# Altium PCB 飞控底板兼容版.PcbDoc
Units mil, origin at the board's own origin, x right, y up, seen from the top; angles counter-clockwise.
Board outline 1946.25 x 1781.68 mil, 4 copper layers (Top Layer, GND, VCC, Bottom Layer), stack 30.634 mil thick; 58 components, 74 nets, 313 pads, 169 vias.
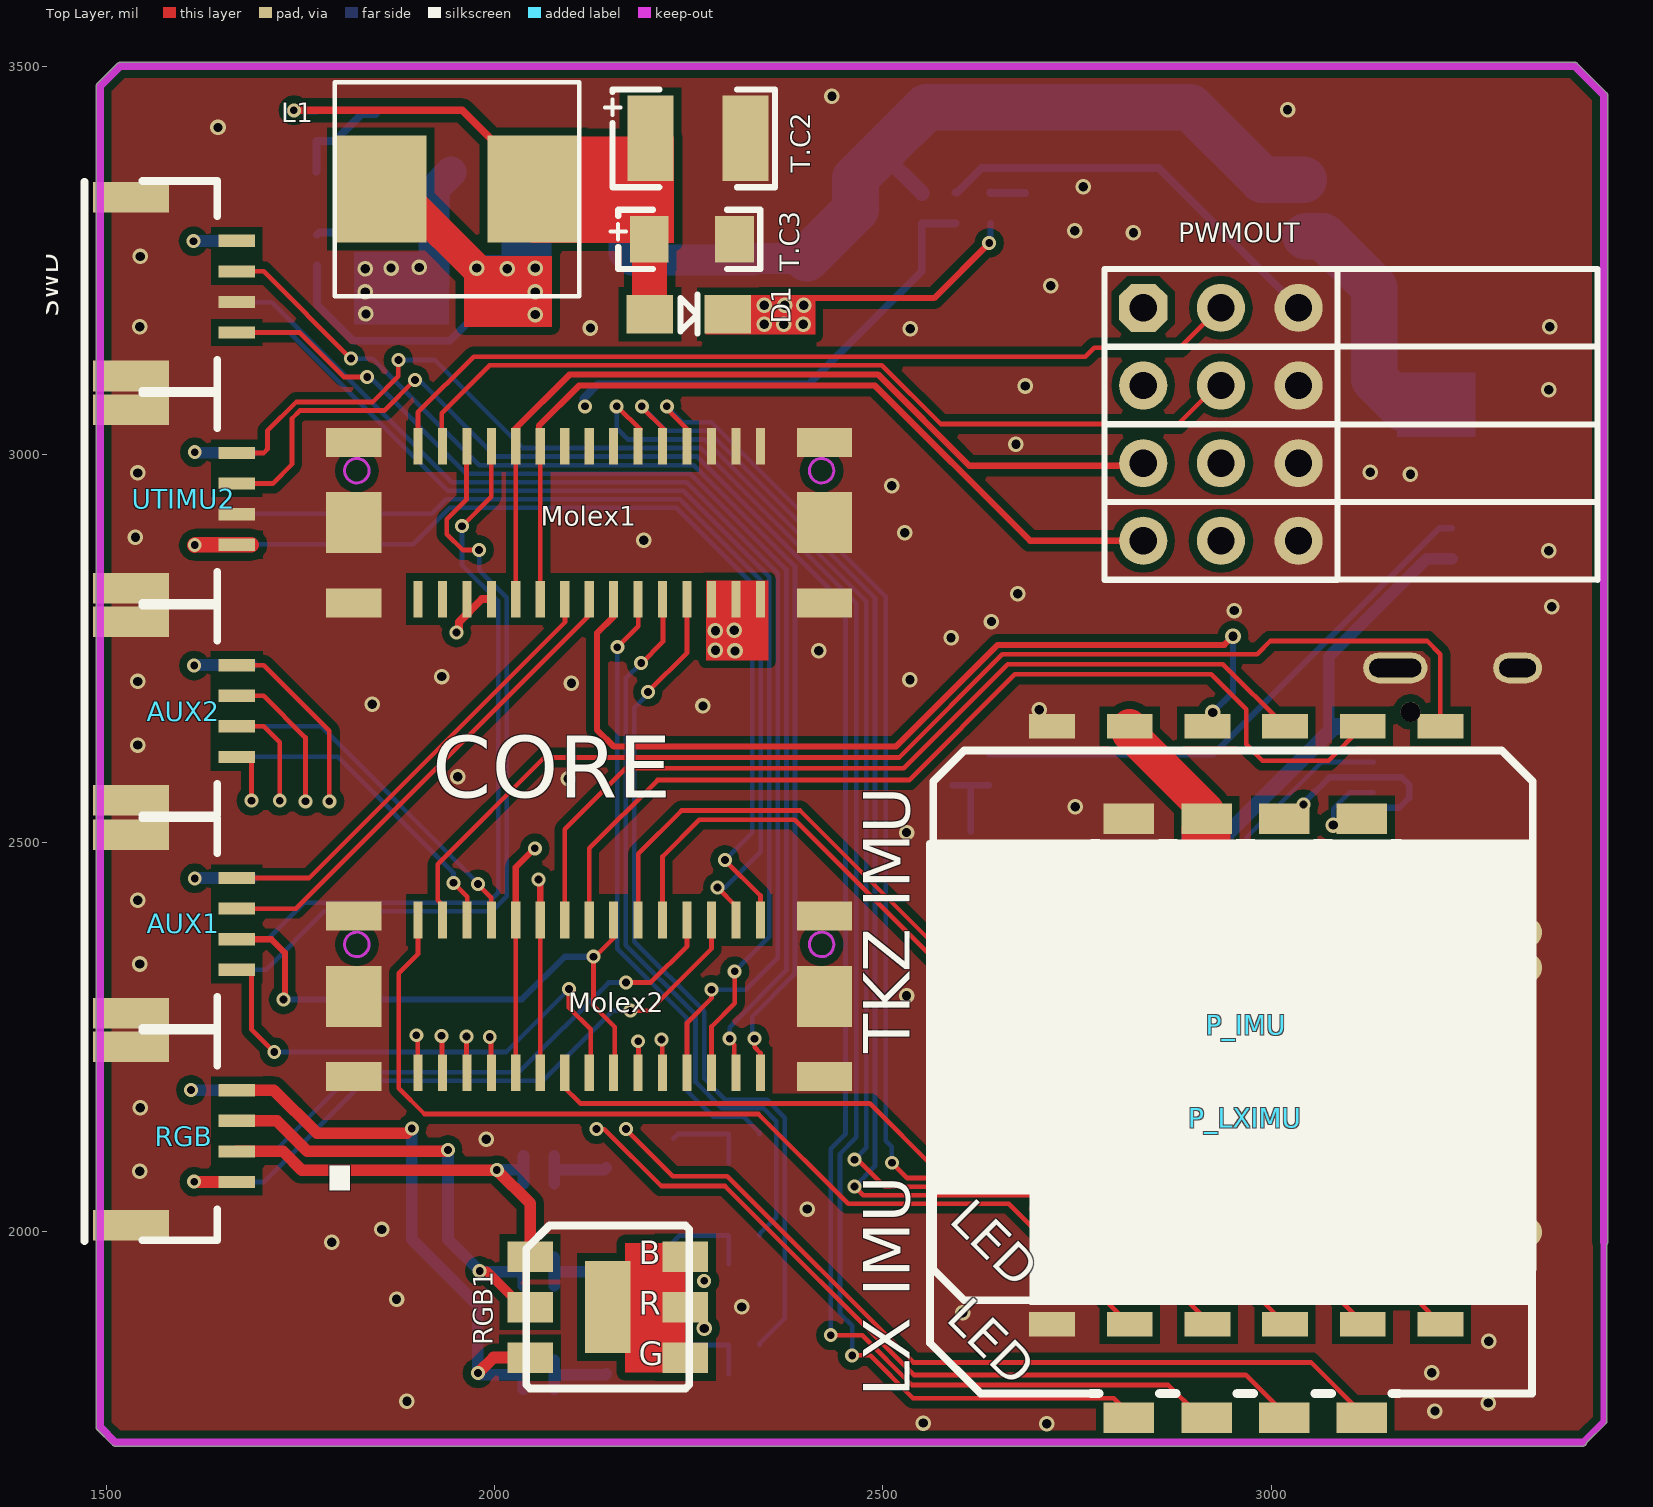
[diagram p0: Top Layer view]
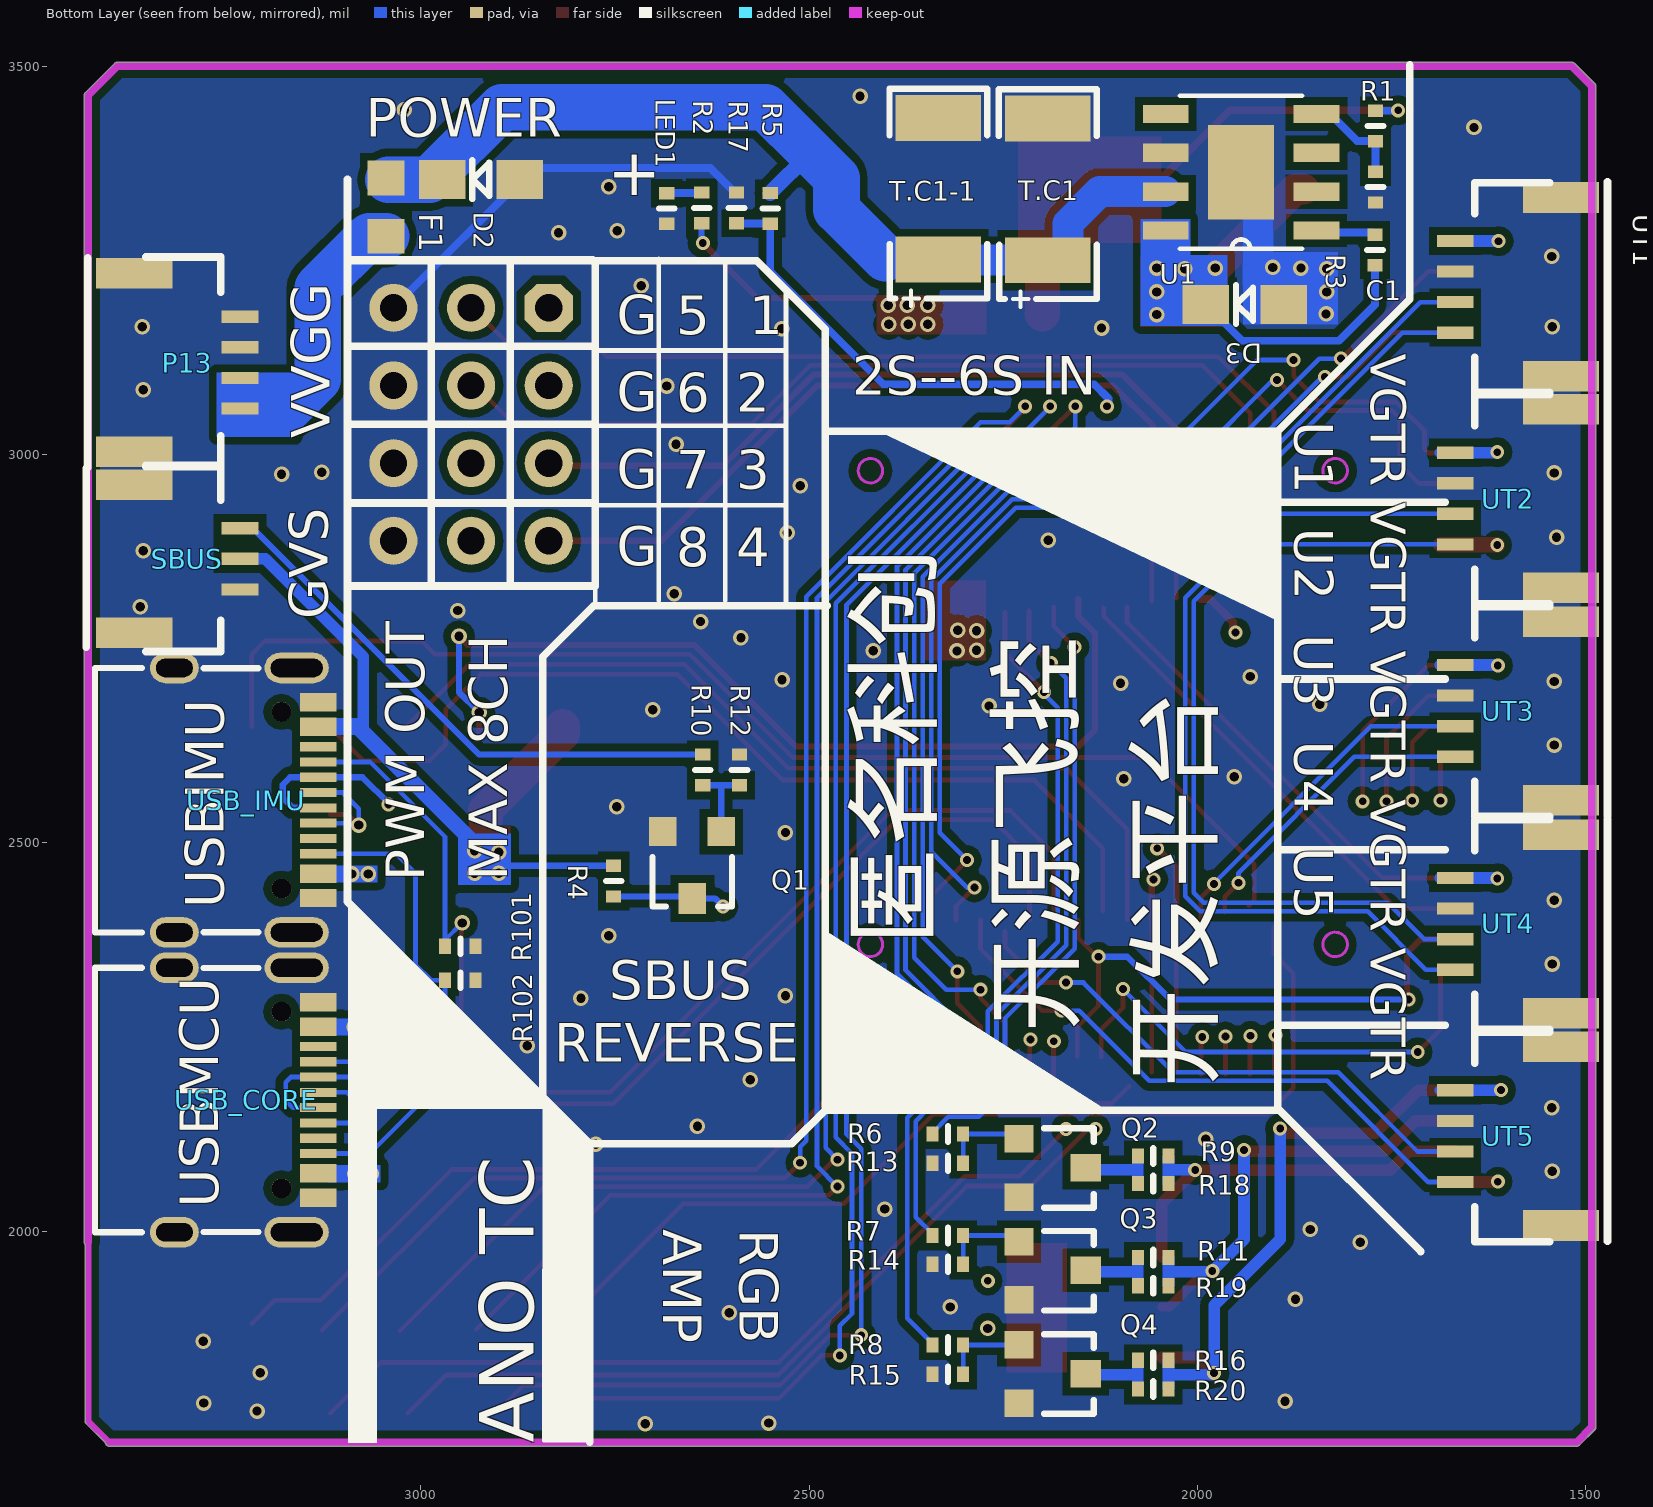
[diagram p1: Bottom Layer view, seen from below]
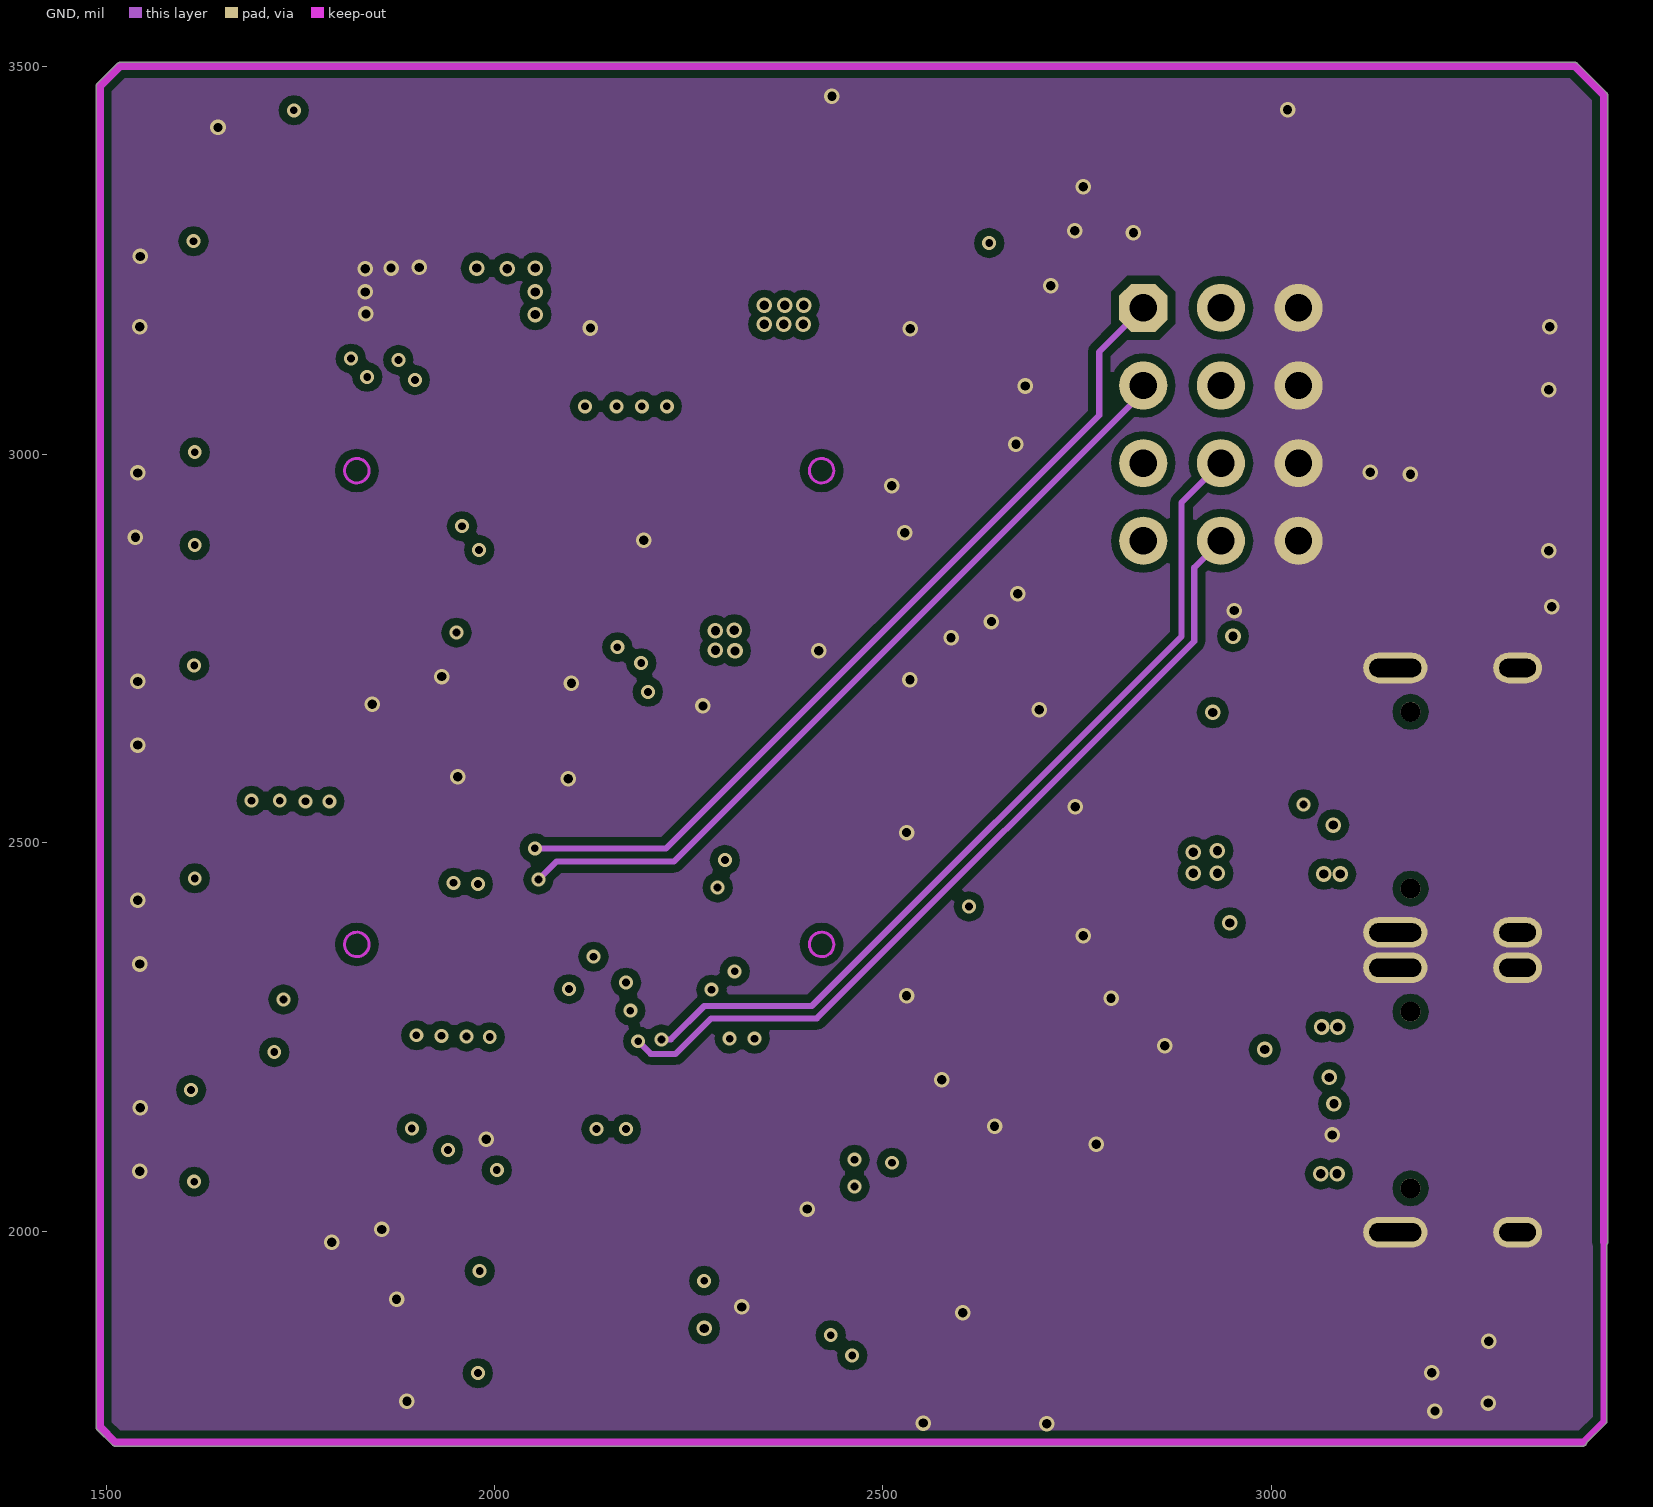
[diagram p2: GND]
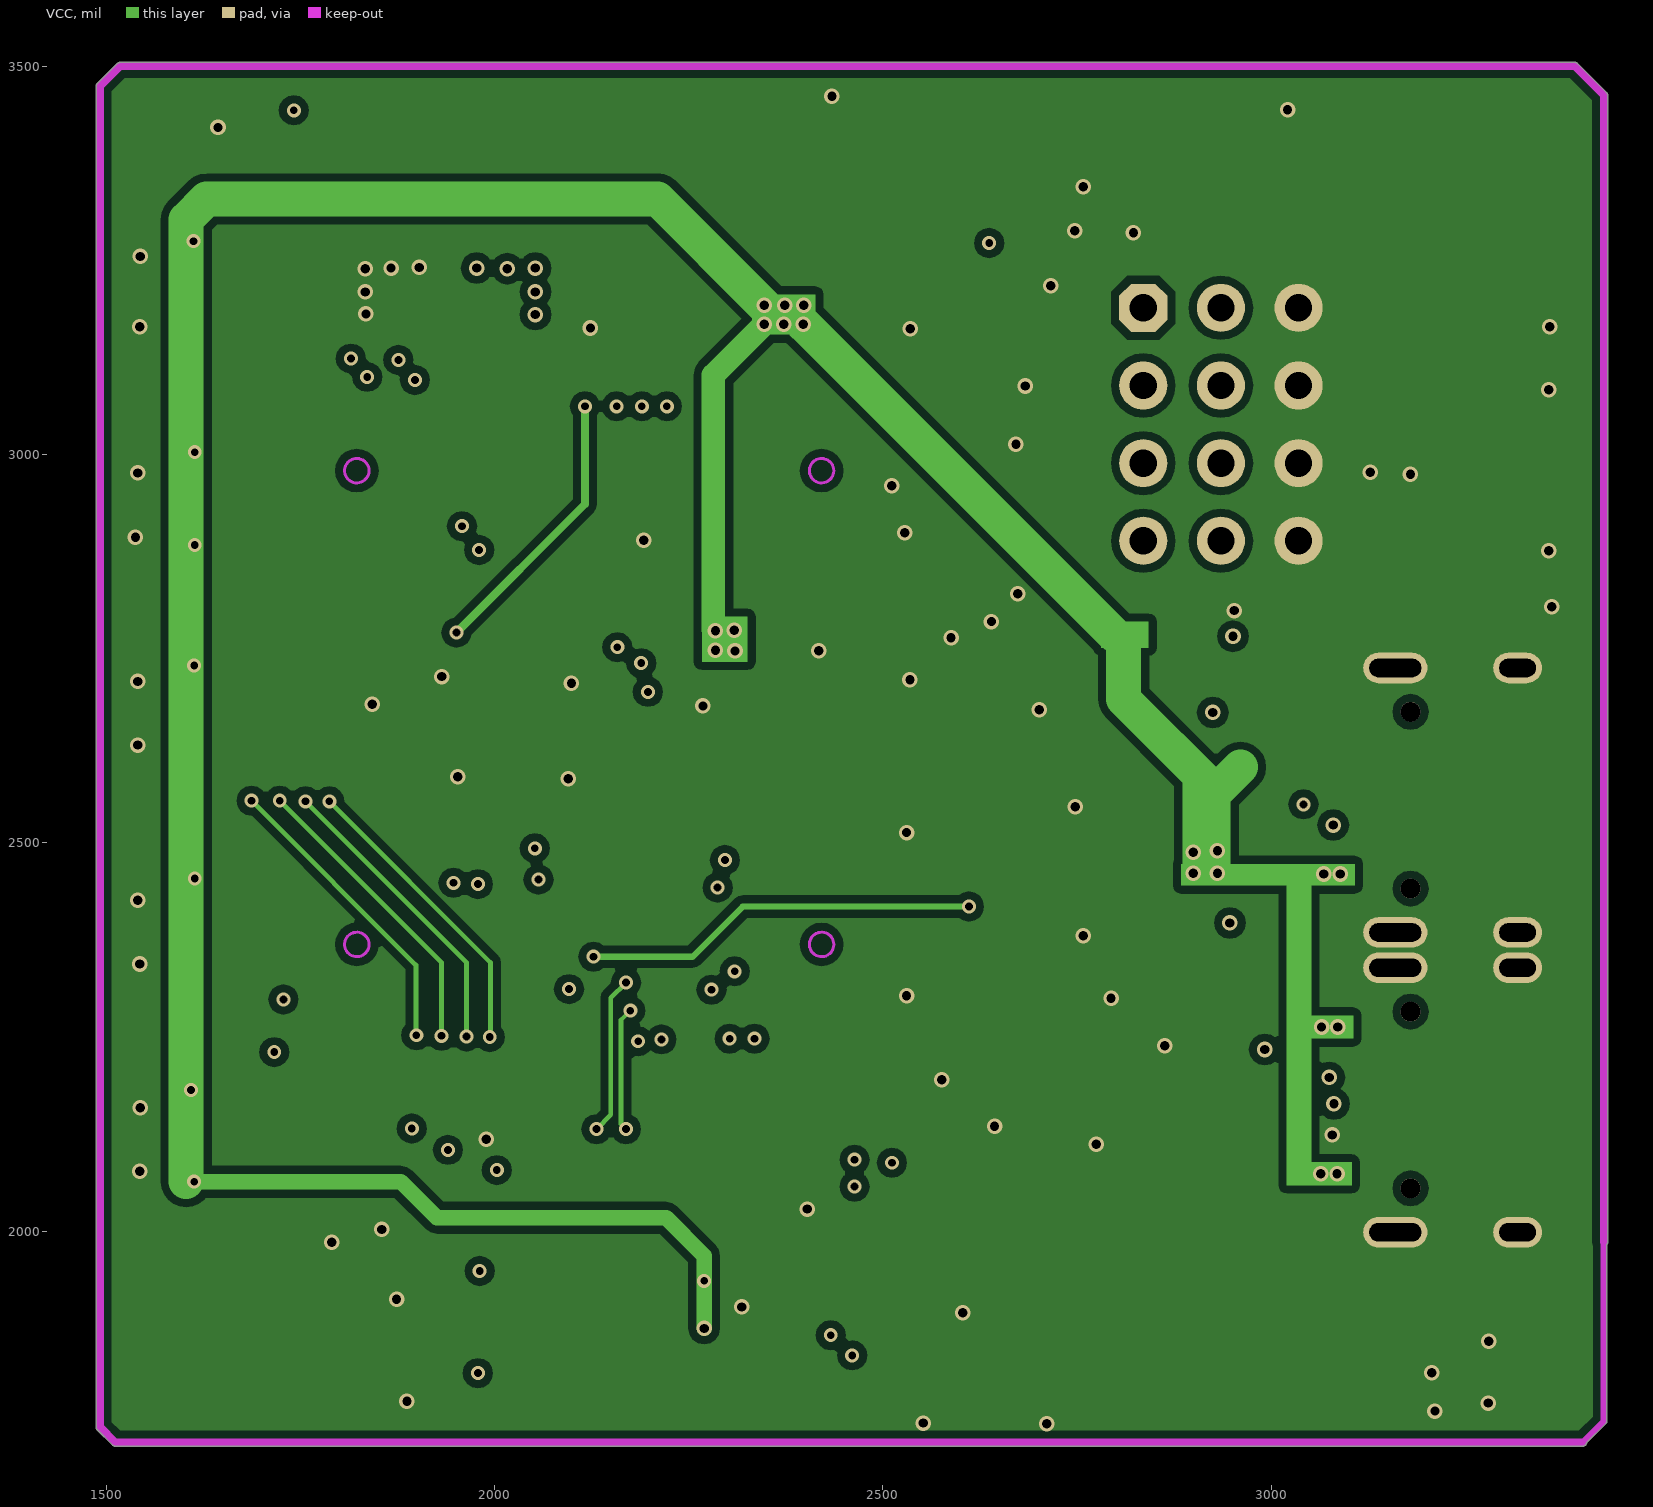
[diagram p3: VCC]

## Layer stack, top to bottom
Top Solder: solder mask 0.4, Solder Resist, Dk 3.5
Top Layer: signal copper 1.4
Dielectric1: core 10, FR-4, Dk 4.2
GND: signal copper 1.417
Dielectric2: prepreg 5, Dk 4.2
VCC: signal copper 1.417
Dielectric3: core 10, Dk 4.2
Bottom Layer: signal copper 1.4
Bottom Solder: solder mask 0.4, Solder Resist, Dk 3.5

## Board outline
1508.11,1724.8 1488.58,1744.33 1488.6,1744.31 cw(c1492.13,1747.87) 1487.11,1747.87 1487.11,3474.13 cw(c1492.13,3474.13) 1488.6,3477.69 1488.58,3477.67 1514.45,3503.55 1514.44,3503.53 cw(c1518,3500) 1518,3505.01 3391,3505.01 cw(c3391,3500) 3394.56,3503.53 3394.55,3503.55 3431.89,3466.2 3431.88,3466.22 cw(c3428.35,3462.65) 3433.36,3462.65 3433.36,1986 cw(c3428.35,1986) 3432.36,1982.99 3432.36,1755.35 cw(c3428.35,1755.35) 3431.17,1752.49 3431.19,1752.51 3406.31,1727.63 cw(c3401.35,1728.35) 3401.35,1723.33 1511.65,1723.33 cw(c1511.65,1728.35)

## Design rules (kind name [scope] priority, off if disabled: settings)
Clearance Clearance_1 [InPolygon] p1: gap=10
Clearance [All] p2: gap=5
ComponentClearance [All] p1: gap=0 collisioncheckmode=3 verticalgap=0 showdistances=FALSE
FabricationTestpoint [(IsPad And (OnTopLayer Or OnBottomLayer))] p1: side=3 testpointundercomponent=TRUE minsize=40 maxsize=100 preferedsize=60 minholesize=0 maxholesize=40 preferedholesize=32 testpointgrid=1 allowsidetop=TRUE allowsidebottom=TRUE usegrid=TRUE gridtolerance=0.01
HoleSize [All] p1: absolutevalues=TRUE maxlimit=196.85 minlimit=1 maxpercent=80.000 minpercent=20.000
HoleToHoleClearance [All] p1: gap=5 allowstackedmicrovias=TRUE
MinimumSolderMaskSliver [All] p1: minsoldermaskwidth=1
PlaneClearance [All] p1: clearance=10
PlaneConnect [All] p1: planeconnectstyle=Direct reliefexpansion=20 reliefentries=4 reliefconductorwidth=10 reliefairgap=10
PolygonConnect [All] p1: connectstyle=Direct reliefconductorwidth=10 reliefentries=4 polygonreliefangle="90 Angle" airgapwidth=10
RoutingVias [All] p1: holewidth=10 width=18 viastyle="Through Hole" minholewidth=10 minwidth=18 maxholewidth=28 maxwidth=50
SilkToSilkClearance [All] p1: silktosilkclearance=0
SilkToSolderMaskClearance [IsPad] p1: minsilkscreentomaskgap=0 clearancetoexposedcopper=TRUE
SolderMaskExpansion [All] p1: expansion=4
Width [All] p1: maxlimit=100 minlimit=4 preferedwidth=5
21 further rules are at their usual default settings.

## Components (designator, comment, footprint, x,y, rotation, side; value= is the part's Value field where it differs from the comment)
AUX1 "AUX_IO" SH_1.0_卧 1540.06,2280.31 r90 top
AUX2 "AUX_IO" SH_1.0_卧 1540.06,2554.32 r90 top
C1 "10nf50v" 0402_small 1771.65,3263.75 r90 bottom
D1 "IN5822" SOD123 2249.61,3181.86 r90 top
D2 "IN5822" SOD123 2922,3353 r270 bottom
D3 "IN5822" SOD123 1938.59,3192.15 r270 bottom
F1 "Comment" 0805_small 3045,3356 r270 bottom
L1 "CD54‐22uH  2A" L-8X7mm-S 1951.97,3341.73 r180 top
LED1 "red" 0402_small 2683.44,3316.54 r270 bottom
Molex1 "MOLEX_30p_母" MOLEX_30p_ĸ 1901.57,3010.79 r0 top
Molex2 "MOLEX_30p_母" MOLEX_30p_ĸ 1901.57,2400.79 r0 top
P13 "power" SH_1.0_卧 3361,3003 r90 bottom
P_IMU "IMU_TKZ" IMU_TKZ_SM2 2603,1911 r0 top
P_LXIMU "IMU_LX" IMU-LX-SM2 2963,2144 r0 top
PWMOUT "HEAD2.54" HEAD1*3*4W 2835.43,3188.98 r270 top
Q1 "si2310" SOT-23 2650.38,2461.42 r0 bottom
Q2 "si2310" SOT-23 2177.17,2081.9 r270 bottom
Q3 "si2310" SOT-23 2177.17,1949.62 r270 bottom
Q4 "si2310" SOT-23 2177.17,1816.55 r270 bottom
R1 "50k" 0402_small 1770.87,3422.86 r270 bottom
R2 "1k" 0402_small 2638.59,3317.35 r270 bottom
R3 "15k" 0402_small 1770.87,3344.12 r270 bottom
R4 "10K" 0402_small 2751.96,2451.17 r90 bottom
R5 "10k 1%" 0402_small 2550.39,3317.31 r90 bottom
R6 "1k" 0402_small 2321.9,2125.2 r0 bottom
R7 "1k" 0402_small 2321.26,1994.48 r180 bottom
R8 "1k" 0402_small 2321.26,1853.54 r180 bottom
R9 "50" 0402_small 2057.47,2096.86 r0 bottom
R10 "1K" 0402_small 2637,2593.71 r270 bottom
R11 "50" 0402_small 2057.47,1966.13 r0 bottom
R12 "10K" 0402_small 2589.75,2593.71 r270 bottom
R13 "10K" 0402_small 2321.26,2087.41 r180 bottom
R14 "10K" 0402_small 2321.26,1957.49 r180 bottom
R15 "10K" 0402_small 2321.26,1815.76 r180 bottom
R16 "50" 0402_small 2057.47,1833.85 r0 bottom
R17 "1k 1%" 0402_small 2593.69,3317.33 r270 bottom
R18 "50" 0402_small 2057.47,2061.41 r0 bottom
R19 "50" 0402_small 2057.47,1929.91 r0 bottom
R20 "50" 0402_small 2057.47,1796.84 r0 bottom
R101 "5.1K" 0402_small 2949,2367 r180 bottom
R102 "5.1K" 0402_small 2949,2323 r180 bottom
RGB "RGB-VBRG" SH_1.0_卧 1540.06,2007.08 r90 top
RGB1 "RGB-LED" zhuixin_5050RGB 2040.93,2002.36 r0 top
SBUS "SBUS" SH_1.0_3P卧 3362,2772 r90 bottom
SWD "swd" SH_1.0_卧 1540.06,3100.78 r90 top
T.C1 "100uf35V" TAN-C(6032-28) 2192.94,3337.79 r180 bottom
T.C1-1 "100uf35V" TAN-C(6032-28) 2333.87,3338.58 r180 bottom
T.C2 "47uf16V" TAN-B(3528-21) 2262.2,3407.11 r270 top
T.C3 "10uf16V" TAN-A(3216-18) 2254.34,3277.14 r180 top
U1 "TPS5430" R-PDSO-G8 1944.06,3268.51 r0 bottom
USB_CORE "Type-C" Type-C 3282,2169 r270 bottom
USB_IMU "Type-C" Type-C 3282,2555 r270 bottom
UT1 "usart1" SH_1.0_卧 1540.06,3331.5 r270 bottom
UT2 "usart2" SH_1.0_卧 1540.06,3058.87 r270 bottom
UT3 "usart3" SH_1.0_卧 1540.06,2785.44 r270 bottom
UT4 "usart4" SH_1.0_卧 1540.06,2511.23 r270 bottom
UT5 "usart5" SH_1.0_卧 1540.06,2237.81 r270 bottom
UTIMU2 "usart_imu" SH_1.0_卧 1540.06,2827.56 r90 top

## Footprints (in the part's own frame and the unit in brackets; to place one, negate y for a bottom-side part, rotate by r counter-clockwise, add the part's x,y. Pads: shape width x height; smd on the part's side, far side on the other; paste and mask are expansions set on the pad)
0402_small [mm]
  rect 0.4x0.5 smd: 1(-0.508,0) 2(0.492,0)
  silkscreen extent -0.01,-0.25 -0.01,0.25, body extent -0.51,-0.25 0.51,0.25, height 0.51
0805_small [mm]
  rect 1.14x1.2 smd: 1(0,0) 2(1.9,0)
HEAD1*3*4W [mil]
  oct 62x62 hole 35: 1(0,0)
  round 62 hole 35: 2(0,100) 3(0,200) 4(100,0) 5(100,100) 6(100,200) 7(200,0) 8(200,100) 9(200,200) 10(300,0) 11(300,100) 12(300,200)
  silkscreen extent -50,-50 350,585, body extent -43,-51 351,249, height 336
IMU-LX-SM2 [mil]
  rect 65x39.37 smd: 1(-146,387) 2(-46,387) 3(54,387) 4(154,387) 5(154,-384) 6(54,-384) 7(-46,-384) 8(-146,-384)
  silkscreen extent -402,-353 373,355
IMU_TKZ_SM2 [mil]
  rect 59.06x31.5 smd: 1(115,739) 2(215,739) 3(315,739) 4(415,739) 5(515,739) 6(615,739) 7(615,-31) 8(515,-31) 9(415,-31) 10(315,-31) 11(215,-31) 12(115,-31)
  silkscreen extent -38,0 734,708
L-8X7mm-S [mm]
  rect 3x3.5 smd: 1(-2.5,0) 2(2.5,0)
  silkscreen extent -4,-3.5 4,3.5, body extent -2.79,-2.67 2.92,2.53, height 4.5
MOLEX_30p_ĸ [mm]
  rect 1.8x0.95 smd: 0(-2.1,-5.125) 0(-2.1,0.125) 0(13.3,-5.125) 0(13.3,0.125)
  rect 1.8x2 smd: 0(-2.1,-2.5) 0(13.3,-2.5)
  rect 0.3x1.2 smd: 1(11.2,0) 2(10.4,0) 3(9.6,0) 4(8.8,0) 5(8,0) 6(7.2,0) 7(6.4,0) 8(5.6,0) 9(4.8,0) 10(4,0) 11(3.2,0) 12(2.4,0) 13(1.6,0) 14(0.8,0) 15(0,0) 16(0,-5) 17(0.8,-5) 18(1.6,-5) 19(2.4,-5) 20(3.2,-5) 21(4,-5) 22(4.8,-5) 23(5.6,-5) 24(6.4,-5) 25(7.2,-5) 26(8,-5) 27(8.8,-5) 28(9.6,-5) 29(10.4,-5) 30(11.2,-5)
  Keep-Out Layer circle w0.1: c-2,-0.8 r0.4
  Keep-Out Layer circle w0.1: c13.2,-0.8 r0.4
R-PDSO-G8 [mil]
  rect 59.06x23.62 smd: 1(-97,-20) 2(-97,-70) 3(-97,-120) 4(-97,-170) 5(97,-170) 6(97,-120) 7(97,-70) 8(97,-20)
  rect 85x122 smd paste-60.5: 9(0,-95)
  silkscreen extent -78,-194 78,4, body extent -122,-194 122,4, height 67
SH_1.0_3P卧 [mm]
  rect 1x2.5 smd: 0(-0.039,0.178) 0(4.803,0.178)
  rect 0.4x1.2 smd: 1(1.381,-3.279) 2(2.381,-3.279) 3(3.381,-3.279)
  silkscreen extent -0.65,-2.64 5.45,1.75
SH_1.0_卧 [mm]
  rect 0.4x1.2 smd: 1(1.432,-3.254) 2(2.432,-3.254) 3(3.432,-3.254) 4(4.432,-3.254)
  rect 1x2.5 smd: 5(0.011,0.203) 5(5.853,0.203)
  silkscreen extent -0.5,-2.62 6.39,1.73, body extent -0.05,-3.43 5.95,1.53, height 3.14
SOD123 [mil]
  rect 50x60 smd: 1(-1.06,49.34) 2(-1.06,-50.66)
  silkscreen extent -26,-12 24,10
SOT-23 [mm]
  rect 0.9x0.95 smd: 1(-0.94,-1.346) 2(0.965,-1.346)
  rect 0.9x1 smd: 3(0,0.838)
  silkscreen extent -1.29,-0.52 1.31,1.1, body extent -1.42,-1.63 1.48,1.17, height 1.3
TAN-A(3216-18) [mil]
  rect 50x60 smd: 1(55,0) 2(-55,0)
  silkscreen extent -88,-38 105,38, body extent -75,-30 75,30, height 39
TAN-B(3528-21) [mm]
  rect 2.8x1.5 smd: 1(0,-1.55) 2(0,1.55)
  silkscreen extent -1.6,-3.05 1.6,2.51
TAN-C(6032-28) [mm]
  rect 2.8x1.5 smd: 1(0,-2.222) 2(0,2.413)
  silkscreen extent -1.6,-3.75 1.6,3.37
Type-C [mm]
  round 0.65 hole 0.65: 0(-2.89,2.6) 0(2.89,2.6)
  oval 1x1.6 hole 0.6 slot 1.2 at 90 deg: 1(4.325,-0.9) 2(-4.325,-0.9)
  oval 1x2.1 hole 0.6 slot 1.7 at 90 deg: 3(-4.325,3.1) 4(4.325,3.1)
  rect 0.3x1.2 smd: A1(-3.35,3.8) A4(-2.55,3.8) A5(-1.25,3.8) A6(-0.25,3.8) A7(0.25,3.8) A8(1.25,3.8) A9(2.55,3.8) A12(3.35,3.8) B1(3.05,3.8) B4(2.25,3.8) B5(1.75,3.8) B6(0.75,3.8) B7(-0.75,3.8) B8(-1.75,3.8) B9(-2.25,3.8) B12(-3.05,3.8)
  silkscreen extent -4.33,-3.5 4.32,1.84, body extent -4.48,-3.5 4.47,4.25, height 3.26
zhuixin_5050RGB [mm]
  rect 1.5x3 smd: 0(2.667,-2.54)
  rect 1.5x1 smd: 1(5.203,-4.191) 2(0.131,-4.191) 3(5.203,-2.54) 4(0.131,-2.54) 5(5.203,-0.889) 6(0.131,-0.889)
  silkscreen extent 0,-5.21 5.33,0.13

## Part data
AUX1 AUX2 P13 RGB SWD UT1 UT2 UT3 UT4 UT5 UTIMU2: library part "Header 4", "Header, 4-Pin"
C1: library part CAP_0402
D1 D2 D3: library part IN5822-SS34, "肖特基二极管"
L1: library part L
LED1: library part D-LED, "LED"
Molex1 Molex2: library part MOLEX_30p_ĸ
PWMOUT: library part HEAD1*3*4
Q1 Q2 Q3 Q4: library part "MOSFET N"
R1 R2 R3 R4 R5 R6 R7 R8 R9 R10 R11 R12 R13 R14 R15 R16 R17 R18 R19 R20: library part Res, "Resistor"
R101 R102: library part R, "贴片电阻"
SBUS: library part HEADER_3P
T.C1 T.C1-1 T.C2 T.C3: library part "Cap TAN", "TAN Capacitor (Radial)"
U1: "9脚与地连接"
USB_CORE USB_IMU: "typeC"

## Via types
v1: diameter 20, hole 12, Top Layer to Bottom Layer, tented both sides, 105 vias
v2: diameter 18, hole 10, Top Layer to Bottom Layer, tented both sides, 64 vias

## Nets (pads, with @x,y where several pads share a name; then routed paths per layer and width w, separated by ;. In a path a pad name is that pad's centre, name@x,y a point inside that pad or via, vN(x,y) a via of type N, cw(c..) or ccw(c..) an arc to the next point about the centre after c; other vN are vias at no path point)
CC1: R101.1 USB_CORE.A5 USB_IMU.A5 | length 703.9
  Top Layer w6: v1(2947,2397) 2948,2396 2948,2278 v1(2992,2234)
  Bottom Layer w6: v1(2947,2397) R101.1@2969,2375 ; R101.1 R101.1@2969,2375 ; v1(2992,2234) 2996,2230 3078,2230 3089.79,2218.21 USB_CORE.A5 ; USB_IMU.A5 3065.21,2604.21 2969,2508 R101.1@2969,2375
CC2: R102.1 USB_CORE.B5 USB_IMU.B5 | length 629.7
  Bottom Layer w6: USB_CORE.B5 3065.9,2100.1 2969,2197 R102.1 2986.99,2322.99 3007,2343 3007,2461.1 3032,2486.1 USB_IMU.B5
DM: Molex2.6 USB_CORE.A7 USB_CORE.B7 | length 1327.5
  Top Layer w6: Molex2.6 2185.04,2485.83 2240.94,2541.73 2393.51,2541.73 2756.24,2179 3056,2179 v1(3075,2198)
  Bottom Layer w6: v1(3075,2198) 3075.53,2198.53 USB_CORE.B7 3167.47,2198.53 3174,2192 3174,2168 3165.16,2159.16 USB_CORE.A7
DP: Molex2.5 USB_CORE.A6 USB_CORE.B6 | length 1243.5
  Top Layer w6: Molex2.5 2216.54,2482.54 2263.92,2529.92 2386.61,2529.92 2704.72,2211.81 2752.54,2164 v1(3081,2164)
  Bottom Layer w6: USB_CORE.B6 3093.53,2139.47 3081,2152 v1(3081,2164) 3095.84,2178.84 USB_CORE.A6
GND: AUX1.5 AUX2.5 D2.1 D3.1 LED1.2 Molex1.0 Molex1.1 Molex1.2 Molex1.3 Molex2.0 P13.3 P13.4 P13.5 P_IMU.1 P_IMU.12 P_LXIMU.1 PWMOUT.3 PWMOUT.6 PWMOUT.9 PWMOUT.12 Q1.2 Q2.2 Q3.2 Q4.2 R3.2 R12.1 R13.1 R14.1 R15.1 R17.1 R101.2 R102.2 RGB.5 SBUS.0 SBUS.1 SWD.2 SWD.5 T.C1-1.2 T.C1.2 T.C2.2 T.C3.2 U1.6 U1.9 USB_CORE.1 USB_CORE.2 USB_CORE.3 USB_CORE.4 USB_CORE.A1 USB_CORE.A12 USB_CORE.B1 USB_CORE.B12 USB_IMU.1 USB_IMU.2 USB_IMU.3 USB_IMU.4 USB_IMU.A1 USB_IMU.A12 USB_IMU.B1 USB_IMU.B12 UT1.2 UT1.5 UT2.2 UT2.5 UT3.2 UT3.5 UT4.2 UT4.5 UT5.2 UT5.5 UTIMU2.2 UTIMU2.5 | length 725.3
  Bottom Layer w10: R17.1 2595.67,3337.33 2627.34,3369 2855.41,3369 PWMOUT.3
  Bottom Layer w40: D3.1 1894.25,3193.22 1922.05,3221.02 1922.05,3341.49 U1.9
  other v1: 2711,1752 2552,1753 3211.02,1768.5 3279.53,1778.74 1887.4,1781.1 3207,1818 3280.32,1858.27 2603,1895 2318.67,1902.57 1874.02,1912.6 1790.55,1985.83 1855.12,2002.36 2402.67,2028.57 1543.31,2077.17 2775,2112 1989.67,2118.57 3079,2124 2644,2135 1544.09,2159.06 2576,2195 2863,2239 2794,2300 2530.71,2303.15 1543.31,2344.09 2758.27,2380.32 1540.94,2425.98 2530.71,2513.39 2748.03,2546.46 2094.97,2582.66 1953,2585 1540.94,2625.98 2701.57,2671.65 2268.5,2676.38 1842.52,2678.74 2099.21,2705.51 1540.94,2707.87 2535,2710 1932.28,2714.17 2417.5,2747.38 2588,2764 2640,2785 2952.76,2799.21 3361.42,2803.94 2674,2821 3357.48,2876.38 2192.13,2889.76 1537.8,2893.7 2528.35,2899.21 2511.81,2959.84 3179.53,2974.8 1540.94,2976.38 3127.56,2977.17 2671.54,3013.32 3357.48,3083.46 2683.54,3088.32 2535.43,3162.2 2123.62,3162.99 1543.31,3164.57 3359.06,3164.57 1834.65,3181.1 1833.86,3209.45 2716.54,3217.32 1833.86,3239.37 1866.93,3240.16 1903.15,3240.94 1544.09,3255.12 2822.83,3285.83 2747.24,3288.19 2758.27,3344.88 1644.09,3421.26 3021.26,3444.09 2434.65,3461.42
GYR_INT: Molex2.22 P_IMU.7 | length 1256.7
  Top Layer w6: Molex2.22@2088,2187 2110.43,2164.57 2483.46,2164.57 2568.55,2079.48 2960.52,2079.48 3129,1911 3188,1911 P_IMU.7@3218,1881
IO_1: AUX1.1 Molex2.23 | length 630.7
  Top Layer w6: AUX1.1@1687.16,2336.7 1687.16,2260.08 v2(1716.54,2230.71) ; v2(2096.06,2311.81) 2096.06,2287.94 2124,2260 Molex2.23@2124,2224
  Bottom Layer w6: v2(1716.54,2230.71) 2014.96,2230.71 v2(2096.06,2311.81)
IO_2: AUX1.2 Molex2.7 Molex2.24 Q1.3 R4.1 | length 1408.9
  Top Layer w6: v2(2127.56,2353.54) v2@2127.56,2351.56 ; Molex2.7 2153.54,2377.54 v2@2127.56,2351.56 ; Molex2.24@2155,2225 2155,2263 2127.56,2290.44 v2@2127.56,2351.56
  Top Layer w8: AUX1.2 1712.91,2376.07 1730.26,2358.72 1730.26,2300.34 v2(1728.35,2298.43)
  VCC w8: v2(2127.56,2353.54) 2255.12,2353.54 2319.68,2418.11 v2(2611.02,2418.11)
  Bottom Layer w8: v2(1728.35,2298.43) 2035.43,2298.43 2090.55,2353.54 v2(2127.56,2353.54) ; v2(2611.02,2418.11) 2621.34,2428.42 Q1.3 2653.12,2431.16 R4.1
IO_3: AUX1.3 Molex1.23 | length 619.8
  Top Layer w6: AUX1.3 1744.44,2415.44 2121,2792 Molex1.23@2121,2803
IO_4: AUX1.4 Molex1.22 | length 578.9
  Top Layer w6: AUX1.4 1761.36,2454.81 2091,2784.45 Molex1.22@2091,2804
IO_5: AUX2.1 Molex2.16 | length 495.2
  Top Layer w6: AUX2.1@1687.16,2610.71 1687.16,2554.57 v2(1687.4,2554.33) ; v2(1899.51,2252.36) 1901.09,2250.79 Molex2.16@1901.09,2201.97
  VCC w6: v2(1687.4,2554.33) 1899,2342.73 v2@1899,2254.33
IO_6: AUX2.2 Molex2.17 | length 576
  Top Layer w6: AUX2.2 1702.91,2650.08 1723.62,2629.37 v2(1723.62,2554.33) ; v2(1931.8,2251.57) 1932.58,2250.79 Molex2.17@1932.58,2201.97
  VCC w6: v2(1723.62,2554.33) 1931.8,2346.16 v2@1931.8,2253.54
IO_7: AUX2.3 Molex2.18 | length 628.4
  Top Layer w6: AUX2.3 1702.91,2689.45 1756.69,2635.67 v2(1756.69,2553.54) ; Molex2.18@1964.08,2201.97 v2(1964.08,2250.79)
  VCC w6: v2(1756.69,2553.54) 1964,2346.24 v2@1964,2252.76
IO_8: AUX2.4 Molex2.19 | length 681.3
  Top Layer w6: AUX2.4 1702.91,2728.82 1787.4,2644.33 v2(1787.4,2553.54) ; v2(1994,2250) 1995.57,2248.43 Molex2.19@1995.57,2201.97
  VCC w6: v2(1787.4,2553.54) 1995,2345.94 v2@1995,2251.97
LED_1: Molex1.27 R8.1 | length 1096.9
  Top Layer w6: v2(2197.64,2694.49) 2248.03,2744.88 Molex1.27@2248.03,2797
  Bottom Layer w6: v2(2197.64,2694.49) 2197.64,2691.39 2180.27,2674.02 2180.27,2372.84 2270,2283.11 2270,2196.69 2297.45,2169.24 2351.04,2169.24 2373.99,2146.29 2373.99,1888.22 2341.15,1855.38 2341.15,1853.53 R8.1
LED_2: Molex1.26 R7.1 | length 946
  Top Layer w6: v2(2188.98,2731.5) 2188.98,2730.98 2217,2759 Molex1.26@2217,2799
  Bottom Layer w6: v2(2188.98,2731.5) 2169.27,2711.79 2169.27,2368.29 2259,2278.56 2259,2192.13 2292.89,2158.24 2346.48,2158.24 2362.99,2141.73 2362.99,2018.17 2341.27,1996.45 R7.1
LED_3: Molex1.25 R6.2 | length 790
  Top Layer w6: v2(2158.27,2751.97) 2159.06,2752.76 2158.66,2753.15 2158.66,2752.66 2185,2779 Molex1.25@2185,2804
  Bottom Layer w6: v2(2158.27,2751.97) 2158.27,2363.73 2248,2274 2248,2181.13 2281.89,2147.24 2321.2,2147.24 2341.27,2127.18 R6.2
NetC1_1: C1.1 D3.2 L1.2 U1.8 | length 611.8
  Top Layer w40: L1.2@1863.78,3341.73 1874.8,3341.73 1996.85,3219.69 2003.15,3213.39 2003.15,3208.66
  Bottom Layer w10: C1.1 1771.64,3192.92 1818.01,3146.56 1942.59,3146.56 D3.2
  Bottom Layer w40: D3.2 1994.25,3193.22 2031.53,3230.5 2031.53,3240.16 U1.8@2031.53,3280.32
  other v1: 2052.76,3180.32 2052.76,3209.45 2016.54,3239.37 1977.17,3240.16 2052.76,3240.16
NetC1_2: C1.2 U1.1 | length 77.7
  Bottom Layer w10: C1.2 1774.34,3285.81 1844.36,3285.81 U1.1
NetD1_1: D1.1 L1.1 R1.1 T.C2.1 T.C3.1 | length 482.6
  Top Layer w10: v2(1741.73,3443.31) 1958.66,3443.31 2050.39,3351.57 L1.1
  Top Layer w45: T.C3.1 2199.8,3276.67 2199.8,3181.26 D1.1
  Bottom Layer w10: v2(1741.73,3443.31) 1742.52,3443.31 1742.96,3442.87 R1.1
NetLED1_1: LED1.1 R2.1 | length 45.2
  Bottom Layer w10: R2.1 2639,3336.95 2683.04,3336.95 LED1.1
NetQ1_1: Q1.1 R10.2 R12.2 | length 107.2
  Bottom Layer w8: R12.2 2613.38,2574.34 ; Q1.1 2613.38,2574.34 ; R10.2 2613.38,2574.34
NetQ2_1: Q2.1 R6.1 R13.2 | length 112.1
  Bottom Layer w6: Q2.1 2236.48,2125.21 R6.1 R13.2
NetQ3_1: Q3.1 R7.2 R14.2 | length 112
  Bottom Layer w6: Q3.1 2238.03,1994.48 R7.2 R14.2
NetQ4_1: Q4.1 R8.2 R15.2 | length 109.5
  Bottom Layer w6: Q4.1 R8.2 R15.2
NetR1_2: R1.2 R3.1 U1.4 | length 130.1
  Bottom Layer w10: R3.1 R1.2 1771.32,3403.94 1794.77,3403.94 1829.35,3438.51 U1.4
OTG_FS_DM: P_LXIMU.3 USB_IMU.A7 USB_IMU.B7 | length 223.9
  Bottom Layer w6: v2@3041.07,2550.27 v2(3041.73,2549.61)
  Bottom Layer w8: v2@3041.07,2550.27 3075.32,2584.53 USB_IMU.B7 3168.47,2584.53 3178,2575 3178,2558 3165.16,2545.16 USB_IMU.A7
OTG_FS_DP: P_LXIMU.4 USB_IMU.A6 USB_IMU.B6 | length 178.1
  Top Layer w6: v1(3080,2523) 3093.61,2536.61 P_LXIMU.4@3116.99,2536.61
  Bottom Layer w6: USB_IMU.B6 3082.47,2525.47 v1(3080,2523) 3080,2544 3100.84,2564.84 USB_IMU.A6
POWER_INPUT: Molex1.18 Molex1.19 R5.1 R17.2 | length 1047.7
  Top Layer w10: v2(1951.18,2770.87) 1954.33,2774.02 1954.33,2784.54 1983.72,2813.94 Molex1.19
  VCC w10: v2(1951.18,2770.87) 2116.54,2936.22 v2(2116.54,3062.2)
  Bottom Layer w10: v2(2116.54,3062.2) 2114.77,3063.97 2114.77,3072.25 2133.07,3090.55 2404.65,3090.55 2550.38,3236.28 R5.1 2550.71,3297.63 2593.37,3297.63 R17.2
PWMOUT_1: Molex2.11 Molex2.20 PWMOUT.1 | length 1417.8
  Top Layer w6: Molex2.20@2027.57,2204.84 Molex2.11@2027.57,2401.69
  Top Layer w8: Molex2.11@2027.57,2401.69 2027.57,2468.57 v2(2052,2493)
  GND w8: v2@2052,2492.91 2220.99,2492.91 2778.74,3050.67 2778.74,3132.28 PWMOUT.1
PWMOUT_2: Molex2.10 Molex2.21 PWMOUT.4 | length 1304
  Top Layer w6: Molex2.21@2059.07,2204.58 Molex2.10@2059.07,2401.43
  Top Layer w8: v2(2056.72,2452.84) 2055.9,2452.84 2059.07,2456.01 Molex2.10@2059.07,2401.43
  GND w8: v2(2056.72,2452.84) 2079.88,2476 2231,2476 2835.43,3080.43 PWMOUT.4
PWMOUT_3: Molex1.11 Molex1.20 PWMOUT.7 | length 1086.2
  Top Layer w6: Molex1.20@2027.57,2814.94 Molex1.11@2027.57,3011.79
  Top Layer w8: Molex1.11@2025.74,3031.74 2097.15,3103.15 2493.98,3103.15 2611.55,2985.57 2832.03,2985.57 PWMOUT.7
PWMOUT_4: Molex1.10 Molex1.21 PWMOUT.10 | length 1087.9
  Top Layer w6: Molex1.21@2059.07,2810.94 Molex1.10@2059.07,3007.79
  Top Layer w8: Molex1.10@2057.54,3028.54 2057.54,3037.54 2108.98,3088.98 2489.76,3088.98 2689.76,2888.98 PWMOUT.10
PWMOUT_5: Molex1.15 PWMOUT.2 | length 1125.1
  Top Layer w6: Molex1.15@1901.57,3019 1901.57,3054.49 1973.24,3126.15 2760.8,3126.15 2772.44,3137.8 2882.68,3137.8 2933.86,3188.98 PWMOUT.2
PWMOUT_6: Molex1.14 PWMOUT.5 | length 1109.4
  Top Layer w6: Molex1.14@1932,3025 1932,3053.42 1993.73,3115.15 2498.95,3115.15 2574.73,3039.37 2880.32,3039.37 2929.92,3088.98 PWMOUT.5
PWMOUT_7: Molex2.26 PWMOUT.8 | length 1173.9
  Top Layer w6: Molex2.26@2215,2202.91 2216.18,2204.09 2216.18,2245.82 v2(2215,2247)
  GND w8: v2(2215,2247) 2227,2247 2270,2290 2408.9,2290 2884.65,2765.75 2884.65,2938.19 PWMOUT.8
PWMOUT_8: Molex2.25 PWMOUT.11 | length 1133.2
  Top Layer w6: v2(2185.08,2244.64) 2188.23,2241.49 2187.87,2241.49 2185.47,2239.09 2185.47,2200.94 Molex2.25@2185.87,2200.54
  GND w8: v2(2185.08,2244.64) 2201.37,2228.35 2233.35,2228.35 2279,2274 2415.2,2274 2901,2759.8 2901,2854.54 PWMOUT.11
R1: Q2.3 R9.2 R18.2 | length 103.9
  Bottom Layer w15: R18.2 2076.83,2079.14 ; R9.2 2076.83,2079.14 ; Q2.3 2141.41,2079.14 2076.83,2079.14
R2: Q3.3 R11.2 R19.2 | length 104.2
  Bottom Layer w15: R19.2 2076.83,1948.03 ; R11.2 2076.83,1948.03 ; Q3.3 2142.58,1948.03 2076.83,1948.03
R3: Q4.3 R16.2 R20.2 | length 104.8
  Bottom Layer w15: R20.2 2076.83,1815.35 ; R16.2 2076.83,1815.35 ; Q4.3 2142.98,1815.35 2076.83,1815.35
R4: R9.1 R18.1 RGB1.6 RGB.2 | length 544.1
  Top Layer w15: RGB.2 1727.87,2102.84 1751.97,2078.74 v2(2003.15,2078.74) 2046.09,2035.8 RGB1.6
  Bottom Layer w15: v2(2003.15,2078.74) 2003.55,2079.14 2037.46,2079.14 ; R18.1 2037.46,2079.14 ; R9.1 2037.46,2079.14
R5: R11.1 R19.1 RGB1.4 RGB.3 | length 638.8
  Top Layer w12: v2(1981.1,1948.82) 1989.78,1948.82 2036.24,1902.36 RGB1.4
  Top Layer w15: RGB.3 1720,2142.21 1758.98,2103.22 1938.66,2103.22 v2(1940.16,2104.72)
  Bottom Layer w15: v2(1940.16,2104.72) 1940.16,1989.76 v2(1981.1,1948.82) 1981.89,1948.03 2037.46,1948.03 ; R19.1 2037.46,1948.03 ; R11.1 2037.46,1948.03
R6: R16.1 R20.1 RGB1.2 RGB.4 | length 773.6
  Top Layer w15: RGB.4 1716.06,2181.58 1771.65,2125.98 1887.4,2125.98 v2(1893.7,2132.28) ; v2(1978.74,1817.32) 1998.77,1837.36 RGB1.2
  Bottom Layer w15: v2(1893.7,2132.28) 1893.7,1989.76 1978.74,1904.72 v2(1978.74,1817.32) 1980.71,1815.35 2037.46,1815.35 ; R20.1 2037.46,1815.35 ; R16.1 2037.46,1815.35
SBUS_IN: R10.1 SBUS.3 | length 716.6
  Bottom Layer w8: R10.1 2925.02,2613.71 3216.44,2905.13 SBUS.3
SPI2_CS1: Molex1.4 P_IMU.8 | length 1867.6
  Top Layer w6: v2@2222.05,3068.2 v2(2222.05,3062.2) 2222.05,3058.95 Molex1.4@2249,3032 ; v2(2511.81,2088.19) 2531.52,2068.48 2931.52,2068.48 P_IMU.8@3127.5,1872.5
  Bottom Layer w6: v2@2222.05,3061.42 2241.97,3041.5 2279.49,3041.5 2504,2816.99 2504,2116.47 2511.81,2108.66 v2(2511.81,2088.19)
SPI2_CS2: Molex1.6 P_IMU.9 | length 1865.7
  Top Layer w6: v2@2157.48,3061.42 2159.06,3059.84 2159.06,3061.13 Molex1.6@2188.19,3032 ; v2(2463.78,2092.13) 2467.72,2092.13 2502.36,2057.48 2841.52,2057.48 P_IMU.9@3027,1872
  Bottom Layer w6: v2@2157.48,3061.42 2157.48,3033.67 2171.65,3019.5 2270.38,3019.5 2479,2810.88 2479,2107.35 v2(2463.78,2092.13)
  other v2: 2157.48,3062.2
SPI2_CS3: Molex1.5 P_IMU.10 | length 1753.7
  Top Layer w6: v2@2189.76,3061.42 2190.55,3060.63 2190.55,3060.45 Molex1.5@2219,3032 ; v2(2463.78,2057.48) 2474.78,2046.48 2756.52,2046.48 P_IMU.10@2929,1874
  Bottom Layer w6: v2@2189.76,3061.42 2220.68,3030.5 2274.94,3030.5 2490,2815.43 2490,2083.7 v2(2463.78,2057.48)
  other v2: 2189.76,3062.2
SPI2_MISO: Molex2.8 P_IMU.5 | length 1260.3
  Top Layer w6: Molex2.8@2122,2412 2122,2492.87 2210.07,2580.93 2533.93,2580.93 2670,2717 2923,2717 2968,2672 2968,2627 2989,2606 3074,2606 P_IMU.5
SPI2_MOSI: Molex2.9 P_IMU.4 | length 1165.3
  Top Layer w6: Molex2.9 2090.55,2517.55 2169,2596 2527,2596 2661,2730 2938,2730 P_IMU.4
SPI2_NSS: Molex2.15 P_IMU.11 | length 1297.1
  Top Layer w6: Molex2.15@1901.57,2392 1901.57,2356.69 1877,2332.12 1877,2184 1910,2151 2340,2151 2455.52,2035.48 2662.52,2035.48 P_IMU.11@2826.5,1871.5
SPI2_SCK: Molex2.14 P_IMU.6 | length 1566.7
  Top Layer w6: Molex2.14@1934,2419 1927,2426 1927,2472.76 2064.24,2610 2521,2610 2654,2743 2982,2743 2999,2760 3201,2760 3218,2743 P_IMU.6
SWCLK_I: Molex2.30 SWD.3 | length 1542.2
  Top Layer w6: SWD.3 1702.91,3235.9 v2(1815.19,3123.62) ; v2(2335,2248) 2335,2237 2342.52,2229.48 Molex2.30@2342.52,2219
  Bottom Layer w6: v2(1815.19,3123.62) 1843.31,3123.62 1980.43,2986.5 2256.71,2986.5 2387,2856.21 2387,2331.29 2332,2276.29 2332,2248 v2(2335,2248)
SWDIO_I: Molex2.29 SWD.1 | length 1517.7
  Top Layer w6: SWD.1 1749.13,3157.16 1806.3,3100 v2(1836.22,3100) ; v2(2303,2248) 2301,2248 2309,2240 Molex2.29@2309,2203.94
  Bottom Layer w6: v2(1836.22,3100) 1839.37,3100 1963.87,2975.5 2252.15,2975.5 2376,2851.65 2376,2335.84 2303,2262.84 v2(2303,2248)
TIM10_CH1: Molex1.24 P_IMU.3 | length 1200.6
  Top Layer w8: Molex1.24 2153.54,2791.54 2132,2770 2132,2646 2154,2624 2517,2624 2648,2755 2940,2755 v1(2951,2766) ; P_IMU.3@2925,2640 v1(2925,2668)
  Bottom Layer w8: v1(2925,2668) 2951,2694 v1(2951,2766)
USART1_RX_I: Molex2.28 UT1.4 | length 1485.5
  Top Layer w6: Molex2.28 2279.53,2263.53 2309.45,2293.45 v2(2309.45,2334.65)
  Bottom Layer w6: UT1.4 1736.7,3157.01 1940.2,2953.5 2243.04,2953.5 2354,2842.54 2354,2379.2 v2(2309.45,2334.65)
USART1_TX_I: Molex2.27 UT1.3 | length 1559
  Top Layer w6: Molex2.27 2248.03,2268.5 2279.53,2300 v2(2279.53,2311.02)
  Bottom Layer w6: UT1.3 1713.07,3196.38 1944.95,2964.5 2247.6,2964.5 2365,2847.09 2365,2352.4 2323.62,2311.02 v2(2279.53,2311.02)
USART2_RX_I: Molex2.1 UT2.4 | length 1175.9
  Top Layer w6: v2(2296.85,2477.95) 2342.52,2432.28 Molex2.1@2342.52,2415
  Bottom Layer w6: UT2.4 1895.39,2884.37 1942.52,2931.5 2233.93,2931.5 2332,2833.43 2332,2513.1 v2(2296.85,2477.95)
USART2_TX_I: Molex2.2 UT2.3 | length 1212.6
  Top Layer w6: v2(2287.4,2442.52) 2285.04,2440.16 2285.04,2444.75 2287.33,2442.45 2311.02,2418.76 Molex2.2
  Bottom Layer w6: UT2.3 1919.21,2923.74 1937.96,2942.5 2238.49,2942.5 2343,2837.98 2343,2488.67 2296.85,2442.52 v2(2287.4,2442.52)
USART3_RX_I: Molex2.13 UT3.4 | length 399
  Top Layer w6: v2(1947.24,2448.57) 1965,2430.82 Molex2.13@1965,2411
  Bottom Layer w6: UT3.4 1798.06,2610.94 1947.24,2461.76 v2(1947.24,2448.57)
USART3_TX_I: Molex2.12 UT3.3 | length 448.6
  Top Layer w6: v2(1978.74,2447) 1996.06,2429.68 Molex2.12
  Bottom Layer w6: UT3.3 1776.87,2650.31 v2@1979.46,2447.72
USART4_RX_I: Molex1.13 UT4.4 | length 1008.7
  Top Layer w6: Molex1.13@1964,2998 1964,2942 1938.58,2916.58 1938.58,2897.64 1959.06,2877.17 v2(1980.32,2877.17)
  Bottom Layer w6: UT4.4 1706.02,2336.73 1781.13,2411.83 1996.39,2411.83 2016,2431.44 2016,2815.5 1980.32,2851.18 v2(1980.32,2877.17)
USART4_TX_I: Molex1.12 UT4.3 | length 957.6
  Top Layer w6: v2(1958.27,2907.87) 1996,2945.61 Molex1.12@1996,2997
  Bottom Layer w6: UT4.3 1708.39,2376.1 1755.12,2422.83 1991.83,2422.83 2005,2436 2005,2810.94 1958.27,2857.67 v2(1958.27,2907.87)
USART5_RX_I: Molex2.3 P_LXIMU.5 UT5.4 | length 2032.2
  Top Layer w6: v2(2169.29,2131.5) 2229.79,2071 2299.67,2071 2539.67,1831 3051.6,1831 P_LXIMU.5@3116.99,1765.61 ; v2(2175,2284) 2200.25,2284 ; 2200.25,2284.25 2279.53,2363.53 Molex2.3
  VCC w6: v2(2169.29,2131.5) 2163,2137.79 2163,2272 v2(2175,2284)
  Bottom Layer w6: UT5.4 1702.91,2063.31 1833.33,2193.72 2062.23,2193.72 2152.5,2284 v2(2175,2284)
USART5_TX_I: Molex2.4 P_LXIMU.6 UT5.3 | length 1949.7
  Top Layer w6: v2(2131.5,2131.5) 2141.5,2131.5 2214.73,2058.27 2296.84,2058.27 2540.11,1815 2967.6,1815 P_LXIMU.6@3016.99,1765.61 ; v2(2169.49,2320.22) 2201.47,2320.22 ; 2201.47,2320.47 2248.03,2367.03 Molex2.4@2248.03,2386
  VCC w6: v2(2131.5,2131.5) 2150,2150 2150,2300.73 v2(2169.49,2320.22)
  Bottom Layer w6: UT5.3 1716.85,2102.68 1818.9,2204.72 2031.5,2204.72 2146.99,2320.22 v2(2169.49,2320.22)
USART_IMU_RX: P_LXIMU.8 UTIMU2.4 | length 2374
  Top Layer w6: UTIMU2.4 1702.91,3002.05 1707.78,3006.93 1707.78,3030.43 1745.05,3067.69 1843.28,3067.69 1876.38,3100.79 v2(1876.38,3121.84) ; v2(2460.63,1840.16) 2483.84,1840.16 2539,1785 2797.6,1785 P_LXIMU.8@2816.99,1765.61
  Bottom Layer w6: v2(1876.38,3121.84) 1923.04,3121.84 2036.39,3008.5 2265.82,3008.5 2466,2808.32 2466,2121 2445,2100 2445,1893.77 2460.63,1878.14 v2(2460.63,1840.16)
USART_IMU_TX: P_LXIMU.7 UTIMU2.3 | length 2467.5
  Top Layer w6: UTIMU2.3 1714.65,2962.68 1739.37,2987.4 1739.37,3046.46 1749.61,3056.69 1858.27,3056.69 v2(1897.64,3096.06) ; v2(2433.07,1866.14) 2473.41,1866.14 2537.56,1802 2867.78,1802 2904.18,1765.61 P_LXIMU.7@2916.99,1765.61
  Bottom Layer w6: v2(1897.64,3096.06) 1903.15,3096.06 2001.72,2997.5 2261.27,2997.5 2452,2806.76 2452,2125 2433.07,2106.07 v2(2433.07,1866.14)
VCC_3.3V: SWD.4
VCC_5.0V: D1.2 Molex1.28 Molex1.29 Molex1.30 P_IMU.2 P_LXIMU.2 R2.2 R4.2 RGB1.0 RGB1.1 RGB1.3 RGB1.5 RGB.1 SBUS.2 USB_CORE.A4 USB_CORE.A9 USB_CORE.B4 USB_CORE.B9 USB_IMU.A4 USB_IMU.A9 USB_IMU.B4 USB_IMU.B9 UT1.1 UT2.1 UT3.1 UT4.1 UT5.1 UTIMU2.1 | length 5724.5
  Top Layer w8: v1(2398.43,3192.13) 2407.81,3201.51 2566.08,3201.51 v2(2637.01,3272.44)
  Top Layer w15: v2(1613.39,2063.78) 1613.7,2063.47 RGB.1
  Top Layer w20: v2(1614.17,2883.46) 1614.65,2883.95 UTIMU2.1 UTIMU2.1@1687.16,2883.95
  Top Layer w45: P_IMU.2 2818,2641 2917,2542 P_LXIMU.2
  VCC w20: 1603.15,2063.78 v2(1613.39,2063.78) 1879.53,2063.78 1925.98,2017.32 2221.26,2017.32 2270.08,1968.5 v2(2270.08,1936.22) v1(2270.08,1874.8)
  VCC w30: v1@2281.89,2774.8 2281.89,3102.36 v1(2347.24,3167.72)
  VCC w45: 1603.15,2063.78 1603.15,2454.33 1603.15,2883.46 1603.15,3274.8 1603.15,3302.77 1629.51,3329.13 2210.24,3329.13 v1(2347.24,3192.13) ; v1(2397.64,3167.72) 2398.43,3167.72 2797.64,2768.5 ; 2810.24,2762.54 2810.24,2685.04 2929.13,2566.14 2960.63,2597.64
  Bottom Layer w8: v2(2637.01,3272.44) 2637.01,3274.8 2638.59,3276.39 R2.2 ; R4.2 2890.47,2470.53
  Bottom Layer w15: v2(1609.45,2181.89) 1609.92,2181.42 UT5.1 UT5.1@1687.16,2181.42 ; v2(1612.6,3274.8) 1612.91,3275.12 UT1.1 ; v2(1613.39,2728.35) 1614.09,2729.05 UT3.1 UT3.1@1687.16,2729.05 ; v2(1614.17,2454.33) 1614.68,2454.84 UT4.1 UT4.1@1687.16,2454.84 ; v2(1614.17,3003.15) 1614.84,3002.48 UT2.1 UT2.1@1687.16,3002.48 ; 3074.5,2642.5 3074.5,2739.85 3200.41,2865.76 SBUS.2
  Bottom Layer w20: 2932.5,2500.5 3074.5,2642.5 3082,2650
  other v1: 3064,2074 3085,2074 3065,2263 3086,2263 3068,2460 3089,2460 2900,2461 2931,2461 2900,2488 2931,2490 2309.79,2747.23 2284.59,2748.02 2284.59,2773.21 2309,2774 2372.44,3167.72 2374.02,3192.13
VCC_IN: D2.2 F1.1 R5.2 T.C1-1.1 T.C1.1 U1.7 | length 1277.6
  Bottom Layer w20: 2498.5,3389.5 2498.5,3388.56 R5.2
  Bottom Layer w40: U1.7 2126.06,3338.51 2166.93,3297.64 2166.93,3259.82 2176.46,3250.29 T.C1.1 2193.34,3250.68 2333.47,3250.68 T.C1-1.1 2335.36,3252.57 2402,3252.57
  Bottom Layer w60: 2402,3252.57 2465,3315.57 2465,3356 2498.5,3389.5 2556,3447 2896,3447 2989,3354 F1.1@3042,3354
VOL_BAT: F1.2 P13.1 P13.2 | length 425.1
  Bottom Layer w40: 3170.61,3059.39 3186,3044 3204.82,3044 3201.89,3046.93 3233.33,3046.93
  Bottom Layer w60: F1.2 3066.8,3281.2 3133,3215 3133,3097 3170.61,3059.39 P13.1
X_IO_1: Molex1.9
X_IO_2: Molex1.8
X_IO_3: Molex1.7
X_IO_4: Molex1.17
pads on no net: Molex1.16 U1.2 U1.3 U1.5 USB_CORE.0 USB_CORE.A8 USB_CORE.B8 USB_IMU.0 USB_IMU.A8 USB_IMU.B8

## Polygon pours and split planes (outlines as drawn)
GND on Top Layer "gnd" (solid, remove dead copper, pour order 8): 1474,3512 1474,1715 3455,1715 3455,3507 3457,3509
GND on Bottom Layer "gnd" (solid, remove dead copper, pour order 7): 1468.11,3509.04 1468.11,1712.04 3449.11,1712.04 3449.11,3504.04 3451.11,3506.04
GND on GND "gnd" (solid, remove dead copper, pour order 6): 1474,3512 1474,1715 3455,1715 3455,3507 3457,3509
GND on VCC "gnd" (solid, remove dead copper, pour order 5): 1484,3499 1484,1702 3465,1702 3465,3494 3467,3496

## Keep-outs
Keep-Out Layer:
  lines w8: 3401.35,1728.35 3428.35,1755.35 3428.35,1986
  lines w10: 3401.35,1728.35 2663.39,1728.35 1511.65,1728.35 1492.13,1747.87 1492.13,3474.13 1518,3500 2257.87,3500 3391,3500 ; 3428.35,1986 3428.35,3462.65 ; 3391,3500 3428.35,3462.65 ; 3391,3500 3428.35,3462.65

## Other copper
Top Layer:
  rectangle net VCC_5.0V: 2885,2447 2948,2522
  rectangle net VCC_5.0V: 2272.69,2735 2353,2838.15
  rectangle net VCC_5.0V: 2168,1818.07 2245.77,1985
  rectangle net VCC_5.0V: 2271.65,3154.33 2413.39,3205.51
  rectangle net NetD1_1: 2046.46,3272.44 2231.5,3409.45
  rectangle net NetC1_1: 1960.63,3164.57 2074.02,3255.91
VCC:
  rectangle net VCC_5.0V: 3020,2059 3052,2473
  rectangle net VCC_5.0V: 3027,2059 3104,2089
  rectangle net VCC_5.0V: 3029,2248 3106,2278
  rectangle net VCC_5.0V: 2884,2445 3108,2473
  rectangle net VCC_5.0V: 2267,2733 2326.06,2791.27
  rectangle net VCC_5.0V: 2331.5,3154.33 2413.39,3206.3
  rectangle net VCC_5.0V: 2781.1,2751.18 2842.52,2785.04
  rectangle net VCC_5.0V: 2885.83,2450 2948.03,2582.68
Bottom Layer:
  rectangle net VCC_5.0V: 3052,2063 3120,2085
  rectangle net VCC_5.0V: 3053,2252 3121,2274
  rectangle net VCC_5.0V: 3056,2449 3124,2471
  rectangle net VCC_5.0V: 3078,2639 3122,2661
  rectangle net VCC_5.0V: 2884,2446 2952,2512
  rectangle net GND: 1818.9,3167.72 1941.73,3260.63
  rectangle net NetC1_1: 1961.42,3165.35 2073.23,3256.69
  rectangle net NetC1_1: 2009.45,3165.35 2073.23,3303.15
  rectangle net VOL_BAT: 3162,3022.83 3262.99,3106

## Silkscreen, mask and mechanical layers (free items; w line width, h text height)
Top Overlay:
  rectangle: 2560.99,2047 3334,2504.61
  rectangle: 2689,1905 3331,2050
  text "CORE" at 1919.68,2558.27 h80
  text "TKZ IMU" at 2535,2229 h60 r90
  text "." at 1760.63,2051.97 h300
  text "LX IMU" at 2535,1787 h60 r90
Bottom Overlay:
  rectangle: 3056.69,1727.56 3093.7,2170.08
  region: 2843.31,2173.23 2782.68,2112.6 2782.68,1728.35 2842.52,1728.35 2844.09,1729.92
  region: 2827.56,2157.48 3093.7,2157.48 3093.7,2423.62
  region: 2480.32,2387.4 2480.32,2156.69 2477.95,2154.33 2114.96,2154.33
  region: 1896.85,3029.92 1896.85,2785.83 2410.24,3029.92 2139.37,3031.5
  lines w6: 2530,2808 2530,3211 ; 2531,2935 2775.16,2935 ; 2531,3037 2773.61,3037 ; 2531,3134 2770.22,3134 ; 2608,2812 2608,3251 ; 2694,2812 2694,3252 ; 2775.59,2806.3 2775.59,2830.71
  lines w10: 1681.1,2265.35 1894.49,2265.35 ; 1681.1,2491.34 1896.06,2491.34 ; 1681.1,2711.02 1892.91,2711.02 ; 1681.1,2938.58 1891.34,2938.58 ; 1712.6,1974.02 1894.49,2155.91 2479.53,2155.91 ; 1726.77,3501.57 1726.77,3200 1896.85,3029.92 ; 1896.85,2155.91 1896.85,3029.92 ; 2477.17,2805.51 2777.49,2805.51 2843.31,2739.69 2843.31,2173.23 ; 2775.59,3038.98 3092.91,3038.98 ; 2775.59,3139.37 3092.91,3139.37 ; 2777.95,2937.8 3093.7,2937.8 ; 2782.68,1728.35 2782.68,2112.6 ; 2885.04,2830.71 2885.04,3248.82 ; 2986.61,2832.28 2986.61,3248.03 ; 3094.49,3249.61 2567.61,3249.61 2479.53,3161.53 2479.53,3029.92 ; 3094.49,3354.33 3094.49,3250.39 ; 1896.85,3029.92 2479.53,3029.92 ; 2479.53,2155.91 2479.53,3029.92 ; 2479.53,2155.91 2522.83,2112.6 2782.68,2112.6 ; 2782.68,2112.6 2843.31,2173.23 ; 2843.31,2173.23 3094.49,2424.41 3094.49,2830.71 ; 3094.49,2830.71 3094.49,3250.39 ; 3094.49,2830.71 2775.59,2830.71 2775.59,3247.24 2778.74,3250.39 2788.98,3250.39 3094.49,3250.39
  text "POWER" at 3071,3409 h50
  text "+" at 2690.55,3333.86 h60
  text "G" at 2748.18,3155.88 h50
  text "1" at 2577.34,3154.88 h50
  text "5" at 2671,3154.88 h50
  text "VGTR VGTR VGTR VGTR VGTR" at 1777,3130 h45 r90
  text "2S--6S IN" at 2444.88,3077.17 h50
  text "G" at 2748.18,3056.41 h50
  text "2" at 2594,3055.41 h50
  text "6" at 2671,3055.41 h50
  text "U1  U2  U3  U4  U5" at 1875,3043 h50 r90
  text "VVGG" at 3117.32,3021.26 h50 r270
  text "G" at 2748.18,2956.93 h50
  text "3" at 2594,2955.93 h50
  text "7" at 2671,2955.93 h50
  text "G" at 2748.18,2857.46 h50
  text "4" at 2594,2856.46 h50
  text "8" at 2671,2856.46 h50
  text "GVS" at 3119.69,2788.19 h50 r270
  text "MAX 8CH" at 2889,2451 h50 r270
  text "PWM OUT" at 2996.06,2450.39 h50 r270
  text "USBIMU" at 3254,2416 h50 r270
  text "匿名科创" at 2316,2367 h160 r270
  text "SBUS" at 2757.48,2298.43 h50
  text "开源飞控" at 2133,2255 h160 r270
  text "REVERSE" at 2828.35,2218.11 h50
  text "开发平台" at 1954,2184 h160 r270
  text "USBMCU" at 3261,2030 h50 r270
  text "RGB" at 2589.76,2002.36 h50 r90
  text "AMP" at 2688.19,2002.36 h50 r90
  text "ANO TC" at 2831.5,1727.56 h120 r270
Bottom Solder:
  text "ANO TC" at 2904.72,1751.18 h120 r270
